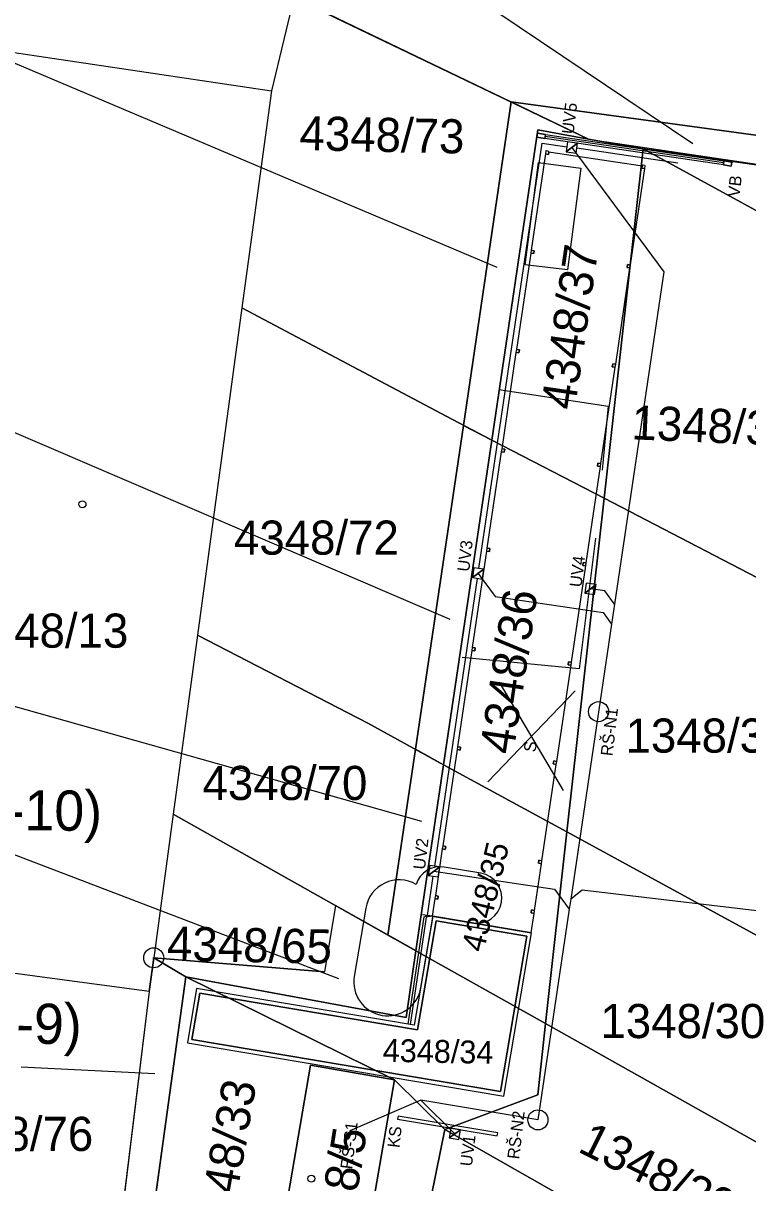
# Model space of a CAD drawing. Extents: x -735036 to -734743, y -1144813 to -1144181.
# Drawn here: x -734893.7 to -734857.6, y -1144559 to -1144501.3 of the extents above; entities that cross this region are included whole.
import ezdxf

# ---------------------------------------------------------------- set-up
doc = ezdxf.new("R2010")
doc.units = 0
for name, color, linetype in [('A3_BOURANÉ OBJEKTY', 7, 'Continuous'), ('A3_ODVODŇOVACÍ ŽLAB', 7, 'Continuous'), ('A3_SIT_OBJEKTY_N01', 7, 'Continuous'), ('A3_SIT_PNB', 7, 'Continuous'), ('CKKOTY', 7, 'Continuous'), ('CKSTENY_SRAF', 7, 'Continuous'), ('CKTEXTY_MALE', 7, 'Continuous'), ('Katastr_HRANICE DRÁHY', 7, 'Continuous'), ('Katastr_Hranice parcel', 7, 'Continuous'), ('Katastr_Parcelní čísla', 7, 'Continuous'), ('Katastr_pozemek SŽDC_šrafy', 7, 'Continuous'), ('Katastr_pozemek_ČD_šrafy', 7, 'Continuous'), ('Katastr_Značky kultur', 7, 'Continuous'), ('SO01_CKKANALIZACE_JEDNOTNA_PODZ_N', 7, 'Continuous'), ('SO05_CKKANALIZACE_JEDNOTNA_PODZ_N', 7, 'Continuous'), ('ZÁBORY_dočasné', 7, 'Continuous'), ('ZÁBORY_dočasné_šrafy', 7, 'Continuous')]:
    doc.layers.add(name, color=color, linetype=linetype)

msp = doc.modelspace()

# ---------------------------------------------------------------- linework, layer by layer
for p, q in [((-734866.625, -1144507.658), (-734866.057, -1144507.237)), ((-734871.293, -1144528.872), (-734870.725, -1144528.45)), ((-734865.695, -1144529.643), (-734865.127, -1144529.221)), ((-734873.494, -1144543.707), (-734872.926, -1144543.285)), ((-734872.456, -1144556.781), (-734871.88, -1144556.371))]:
    msp.add_line(p, q)
for points in [[(-734866.625, -1144507.658), (-734866.13, -1144507.731), (-734866.057, -1144507.237), (-734866.551, -1144507.163)], [(-734866.625, -1144507.658), (-734866.13, -1144507.731), (-734866.057, -1144507.237)], [(-734871.293, -1144528.872), (-734870.798, -1144528.945), (-734870.725, -1144528.45), (-734871.219, -1144528.377)], [(-734871.293, -1144528.872), (-734870.798, -1144528.945), (-734870.725, -1144528.45)], [(-734865.695, -1144529.643), (-734865.201, -1144529.716), (-734865.127, -1144529.221), (-734865.622, -1144529.148)], [(-734865.695, -1144529.643), (-734865.201, -1144529.716), (-734865.127, -1144529.221)], [(-734873.494, -1144543.707), (-734873, -1144543.78), (-734872.926, -1144543.285), (-734873.421, -1144543.212)], [(-734873.494, -1144543.707), (-734873, -1144543.78), (-734872.926, -1144543.285)], [(-734872.456, -1144556.781), (-734871.963, -1144556.864), (-734871.88, -1144556.371), (-734872.373, -1144556.288)], [(-734872.456, -1144556.781), (-734871.963, -1144556.864), (-734871.88, -1144556.371)]]:
    msp.add_lwpolyline(points, close=True)
at = {"layer": 'A3_BOURANÉ OBJEKTY'}
for p, q in [((-734866.751, -1144539.477), (-734869.95, -1144534.072)), ((-734866.175, -1144534.51), (-734870.526, -1144539.039))]:
    msp.add_line(p, q, dxfattribs=at)
msp.add_lwpolyline([(-734866.552, -1144513.548), (-734868.669, -1144513.299), (-734867.996, -1144508.198), (-734865.894, -1144508.483)], close=True, dxfattribs=at)
for points in [[(-734869.977, -1144519.507), (-734864.523, -1144520.336), (-734864.819, -1144523.525)], [(-734865.166, -1144526.906), (-734865.978, -1144533.409), (-734871.807, -1144532.846)]]:
    msp.add_lwpolyline(points, dxfattribs=at)
at = {"layer": 'A3_ODVODŇOVACÍ ŽLAB'}
for points in [[(-734870.972, -1144528.414), (-734867.824, -1144507.227), (-734866.588, -1144507.411)], [(-734861.049, -1144508.234), (-734866.093, -1144507.484)], [(-734873.174, -1144543.249), (-734871.046, -1144528.908)], [(-734874.496, -1144551.113), (-734873.702, -1144545.773), (-734873.54, -1144545.701), (-734873.249, -1144543.743)]]:
    msp.add_lwpolyline(points, dxfattribs=at)
at = {"layer": 'A3_SIT_OBJEKTY_N01'}
for p, q in [((-734867.491, -1144507.64), (-734867.62, -1144507.621)), ((-734867.487, -1144507.681), (-734867.483, -1144507.651)), ((-734862.694, -1144508.352), (-734862.823, -1144508.333)), ((-734873.262, -1144545.743), (-734874.2, -1144551.163)), ((-734874.036, -1144551.393), (-734873.099, -1144545.974)), ((-734868.356, -1144546.569), (-734873.262, -1144545.743)), ((-734873.099, -1144545.974), (-734868.587, -1144546.733)), ((-734869.725, -1144554.704), (-734868.356, -1144546.569)), ((-734868.587, -1144546.733), (-734869.889, -1144554.474)), ((-734885.047, -1144549.338), (-734885.503, -1144552.05)), ((-734874.2, -1144551.163), (-734885.047, -1144549.338)), ((-734885.273, -1144551.886), (-734884.883, -1144549.568)), ((-734884.883, -1144549.568), (-734874.036, -1144551.393)), ((-734885.503, -1144552.05), (-734869.725, -1144554.704)), ((-734869.889, -1144554.474), (-734885.273, -1144551.886)), ((-734875, -1144555.695), (-734875.026, -1144555.843)), ((-734875.026, -1144555.843), (-734870.057, -1144556.677)), ((-734870.032, -1144556.529), (-734875, -1144555.695)), ((-734870.057, -1144556.677), (-734870.032, -1144556.529))]:
    msp.add_line(p, q, dxfattribs=at)
for points in [[(-734867.659, -1144506.797), (-734867.689, -1144506.994), (-734868.084, -1144506.936), (-734868.055, -1144506.738), (-734867.659, -1144506.797)], [(-734888.44, -1144569.554), (-734887.65, -1144563.8), (-734885.58, -1144548.75), (-734874.6, -1144550.79), (-734868.084, -1144506.936)], [(-734858.772, -1144508.218), (-734867.674, -1144506.895)], [(-734867.631, -1144507.629), (-734867.652, -1144507.767), (-734867.504, -1144507.79), (-734867.487, -1144507.681)], [(-734862.834, -1144508.342), (-734862.838, -1144508.372), (-734862.855, -1144508.48), (-734862.706, -1144508.502), (-734862.686, -1144508.364)], [(-734858.391, -1144508.376), (-734858.786, -1144508.317), (-734858.757, -1144508.119), (-734858.361, -1144508.178), (-734858.391, -1144508.376)], [(-734868.216, -1144512.587), (-734868.365, -1144512.565), (-734868.387, -1144512.713), (-734868.238, -1144512.735), (-734868.216, -1144512.587)], [(-734863.419, -1144513.3), (-734863.567, -1144513.278), (-734863.589, -1144513.426), (-734863.441, -1144513.448), (-734863.419, -1144513.3)], [(-734868.951, -1144517.533), (-734869.099, -1144517.511), (-734869.122, -1144517.659), (-734868.973, -1144517.681), (-734868.951, -1144517.533)], [(-734864.154, -1144518.245), (-734864.302, -1144518.223), (-734864.324, -1144518.372), (-734864.176, -1144518.394), (-734864.154, -1144518.245)], [(-734869.686, -1144522.478), (-734869.834, -1144522.456), (-734869.856, -1144522.605), (-734869.708, -1144522.627), (-734869.686, -1144522.478)], [(-734864.889, -1144523.191), (-734865.037, -1144523.169), (-734865.059, -1144523.317), (-734864.911, -1144523.339), (-734864.889, -1144523.191)], [(-734870.421, -1144527.424), (-734870.569, -1144527.402), (-734870.591, -1144527.55), (-734870.443, -1144527.572), (-734870.421, -1144527.424)], [(-734865.623, -1144528.137), (-734865.772, -1144528.115), (-734865.794, -1144528.263), (-734865.645, -1144528.285), (-734865.623, -1144528.137)], [(-734871.156, -1144532.37), (-734871.304, -1144532.348), (-734871.326, -1144532.496), (-734871.178, -1144532.518), (-734871.156, -1144532.37)], [(-734866.358, -1144533.082), (-734866.507, -1144533.06), (-734866.529, -1144533.209), (-734866.38, -1144533.231), (-734866.358, -1144533.082)], [(-734871.89, -1144537.315), (-734872.039, -1144537.293), (-734872.061, -1144537.442), (-734871.912, -1144537.464), (-734871.89, -1144537.315)], [(-734867.093, -1144538.028), (-734867.241, -1144538.006), (-734867.263, -1144538.155), (-734867.115, -1144538.177), (-734867.093, -1144538.028)], [(-734872.625, -1144542.261), (-734872.774, -1144542.239), (-734872.796, -1144542.387), (-734872.647, -1144542.41), (-734872.625, -1144542.261)], [(-734867.828, -1144542.974), (-734867.976, -1144542.952), (-734867.998, -1144543.1), (-734867.85, -1144543.122), (-734867.828, -1144542.974)], [(-734873.163, -1144544.86), (-734873.015, -1144544.882), (-734872.993, -1144544.734), (-734873.141, -1144544.712), (-734873.163, -1144544.86)], [(-734868.195, -1144545.447), (-734868.344, -1144545.425), (-734868.366, -1144545.573), (-734868.217, -1144545.595), (-734868.195, -1144545.447)], [(-734873.262, -1144545.743), (-734873.293, -1144545.738), (-734873.603, -1144545.787), (-734874.397, -1144551.13)]]:
    msp.add_lwpolyline(points, dxfattribs=at)
for points in [[(-734868.055, -1144506.738), (-734868.084, -1144506.936), (-734867.689, -1144506.994), (-734867.659, -1144506.797)], [(-734867.659, -1144506.797), (-734858.757, -1144508.119), (-734858.786, -1144508.317), (-734867.689, -1144506.994)], [(-734869.708, -1144522.627), (-734869.856, -1144522.605), (-734870.569, -1144527.402), (-734870.421, -1144527.424), (-734870.443, -1144527.572), (-734870.591, -1144527.55), (-734871.304, -1144532.348), (-734871.156, -1144532.37), (-734871.178, -1144532.518), (-734871.326, -1144532.496), (-734872.039, -1144537.293), (-734871.89, -1144537.315), (-734871.912, -1144537.464), (-734872.061, -1144537.442), (-734872.774, -1144542.239), (-734872.625, -1144542.261), (-734872.647, -1144542.41), (-734872.796, -1144542.387), (-734873.141, -1144544.712), (-734872.993, -1144544.734), (-734873.015, -1144544.882), (-734873.163, -1144544.86), (-734873.293, -1144545.738), (-734868.362, -1144546.568), (-734868.217, -1144545.595), (-734868.366, -1144545.573), (-734868.344, -1144545.425), (-734868.195, -1144545.447), (-734867.85, -1144543.122), (-734867.998, -1144543.1), (-734867.976, -1144542.952), (-734867.828, -1144542.974), (-734867.115, -1144538.177), (-734867.263, -1144538.155), (-734867.241, -1144538.006), (-734867.093, -1144538.028), (-734866.38, -1144533.231), (-734866.529, -1144533.209), (-734866.507, -1144533.06), (-734866.358, -1144533.082), (-734865.645, -1144528.285), (-734865.794, -1144528.263), (-734865.772, -1144528.115), (-734865.623, -1144528.137), (-734864.911, -1144523.339), (-734865.059, -1144523.317), (-734865.037, -1144523.169), (-734864.889, -1144523.191), (-734864.176, -1144518.394), (-734864.324, -1144518.372), (-734864.302, -1144518.223), (-734864.154, -1144518.245), (-734863.441, -1144513.448), (-734863.589, -1144513.426), (-734863.567, -1144513.278), (-734863.419, -1144513.3), (-734862.706, -1144508.502), (-734862.855, -1144508.48), (-734862.838, -1144508.372), (-734862.937, -1144508.357), (-734867.389, -1144507.696), (-734867.487, -1144507.681), (-734867.504, -1144507.79), (-734867.652, -1144507.767), (-734868.365, -1144512.565), (-734868.216, -1144512.587), (-734868.238, -1144512.735), (-734868.387, -1144512.713), (-734869.099, -1144517.511), (-734868.951, -1144517.533), (-734868.973, -1144517.681), (-734869.122, -1144517.659), (-734869.834, -1144522.456), (-734869.686, -1144522.478)], [(-734858.786, -1144508.317), (-734858.391, -1144508.376), (-734858.361, -1144508.178), (-734858.757, -1144508.119)], [(-734869.725, -1144554.704), (-734868.356, -1144546.569), (-734873.262, -1144545.743), (-734874.2, -1144551.163), (-734885.047, -1144549.338), (-734885.503, -1144552.05)], [(-734869.889, -1144554.474), (-734868.587, -1144546.733), (-734873.099, -1144545.974), (-734874.036, -1144551.393), (-734884.883, -1144549.568), (-734885.273, -1144551.886)], [(-734875.026, -1144555.843), (-734870.057, -1144556.677), (-734870.032, -1144556.529), (-734875, -1144555.695)]]:
    msp.add_lwpolyline(points, close=True, dxfattribs=at)
for centre, start, end in [((-734867.621, -1144507.63), 81.54908, 171.54908), ((-734867.493, -1144507.65), 351.54908, 81.54908), ((-734862.824, -1144508.343), 81.54908, 171.54908), ((-734862.695, -1144508.362), 351.54908, 81.54908)]:
    msp.add_arc(centre, 0.01, start, end, dxfattribs=at)
at = {"layer": 'A3_SIT_PNB'}
for points in [[(-734870.874, -1144543.6), (-734872.698, -1144543.293)], [(-734876.611, -1144545.332), (-734877.183, -1144548.734)], [(-734873.86, -1144549.293), (-734873.287, -1144545.891), (-734873.262, -1144545.743), (-734873.114, -1144545.768), (-734871.29, -1144546.075)]]:
    msp.add_lwpolyline(points, dxfattribs=at)
for centre, radius, start, end in [((-734872.906, -1144544.531), 1.255, 80.4474, 162.539), ((-734871.082, -1144544.838), 1.255, 260.44926, 80.44926), ((-734874.949, -1144545.612), 1.685, 59.88428, 170.44851), ((-734875.521, -1144549.014), 1.685, 170.44926, 350.44926)]:
    msp.add_arc(centre, radius, start, end, dxfattribs=at)
at = {"layer": 'CKKOTY'}
msp.add_line((-734873.293, -1144545.738), (-734873.787, -1144545.665), dxfattribs=at)
at = {"layer": 'CKSTENY_SRAF'}
msp.add_line((-734885.58, -1144548.75), (-734886.194, -1144553.213), dxfattribs=at)
at = {"layer": 'CKTEXTY_MALE'}
for points in [[(-734873.87, -1144554.906), (-734877.406, -1144556.428)], [(-734877.406, -1144556.428), (-734877.429, -1144556.626)]]:
    msp.add_lwpolyline(points, dxfattribs=at)
at = {"layer": 'Katastr_HRANICE DRÁHY'}
for points in [[(-734894.14, -1144502.71), (-734881.31, -1144504.63)], [(-734881.31, -1144504.63), (-734882.78, -1144515.44)], [(-734882.78, -1144515.44), (-734885, -1144531.74)], [(-734885, -1144531.74), (-734886.21, -1144540.66)], [(-734886.21, -1144540.66), (-734887.18, -1144547.81)], [(-734887.18, -1144547.81), (-734885.58, -1144548.75)], [(-734885.58, -1144548.75), (-734887.65, -1144563.8)]]:
    msp.add_lwpolyline(points, dxfattribs=at)
at = {"layer": 'Katastr_Hranice parcel'}
for points in [[(-734865.5, -1144507.03), (-734912.56, -1144484.42)], [(-734868.03, -1144506.57), (-734870.33, -1144522.02)], [(-734868.03, -1144506.57), (-734865.5, -1144507.03)], [(-734865.5, -1144507.03), (-734862.79, -1144507.52)], [(-734862.79, -1144507.52), (-734864.73, -1144524.92)], [(-734852.42, -1144508.98), (-734862.79, -1144507.52)], [(-734852.87, -1144512.92), (-734862.79, -1144507.52)], [(-734882.78, -1144515.44), (-734872.29, -1144521)], [(-734872.29, -1144521), (-734870.33, -1144522.02)], [(-734870.33, -1144522.02), (-734872.73, -1144538.19)], [(-734870.33, -1144522.02), (-734864.73, -1144524.92)], [(-734866.58, -1144541.54), (-734864.73, -1144524.92)], [(-734864.73, -1144524.92), (-734851.62, -1144531.72)], [(-734876.5, -1144536.13), (-734885, -1144531.74)], [(-734872.73, -1144538.19), (-734876.5, -1144536.13)], [(-734872.73, -1144538.19), (-734874.11, -1144547.46)], [(-734866.58, -1144541.54), (-734872.73, -1144538.19)], [(-734874.11, -1144547.46), (-734886.21, -1144540.66)], [(-734867.65, -1144551.09), (-734866.58, -1144541.54)], [(-734852.48, -1144549.23), (-734866.58, -1144541.54)], [(-734887.41, -1144549.49), (-734900.43, -1144547.74)], [(-734874.11, -1144547.46), (-734874.6, -1144550.79)], [(-734867.65, -1144551.09), (-734874.11, -1144547.46)], [(-734887.18, -1144547.81), (-734887.41, -1144549.49)], [(-734874.6, -1144550.79), (-734885.58, -1144548.75)], [(-734885.58, -1144548.75), (-734875.18, -1144553.88)], [(-734868.04, -1144554.63), (-734867.65, -1144551.09)], [(-734853.62, -1144558.97), (-734867.65, -1144551.09)], [(-734881.1, -1144563.24), (-734879.37, -1144553.15)], [(-734879.37, -1144553.15), (-734875.18, -1144553.88)], [(-734875.18, -1144553.88), (-734876.93, -1144563.95)], [(-734875.18, -1144553.88), (-734872.67, -1144556.37)], [(-734872.67, -1144556.37), (-734868.04, -1144554.63)], [(-734875.6, -1144570.76), (-734872.67, -1144556.37)], [(-734854.52, -1144566.67), (-734872.67, -1144556.37)]]:
    msp.add_lwpolyline(points, dxfattribs=at)
at = {"layer": 'Katastr_pozemek SŽDC_šrafy'}
for points in [[(-734862.79, -1144507.52), (-734865.5, -1144507.03), (-734868.03, -1144506.57), (-734870.33, -1144522.02), (-734864.73, -1144524.92), (-734862.79, -1144507.52)], [(-734850.35, -1144520.8), (-734853.72, -1144520.41), (-734852.87, -1144512.92), (-734862.79, -1144507.52), (-734864.73, -1144524.92), (-734851.62, -1144531.72), (-734850.35, -1144520.8)], [(-734852.42, -1144508.98), (-734862.79, -1144507.52), (-734852.87, -1144512.92), (-734852.42, -1144508.98)], [(-734864.73, -1144524.92), (-734870.33, -1144522.02), (-734872.73, -1144538.19), (-734866.58, -1144541.54), (-734864.73, -1144524.92)], [(-734851.62, -1144531.72), (-734864.73, -1144524.92), (-734866.58, -1144541.54), (-734852.48, -1144549.23), (-734851.65, -1144542.13), (-734852.82, -1144541.99), (-734851.62, -1144531.72)], [(-734866.58, -1144541.54), (-734872.73, -1144538.19), (-734874.11, -1144547.46), (-734867.65, -1144551.09), (-734866.58, -1144541.54)], [(-734852.48, -1144549.23), (-734866.58, -1144541.54), (-734867.65, -1144551.09), (-734853.62, -1144558.97), (-734852.48, -1144549.23)], [(-734867.65, -1144551.09), (-734874.11, -1144547.46), (-734874.6, -1144550.79), (-734885.58, -1144548.75), (-734875.18, -1144553.88), (-734872.67, -1144556.37), (-734868.04, -1144554.63), (-734867.65, -1144551.09)], [(-734879.37, -1144553.15), (-734875.18, -1144553.88), (-734885.58, -1144548.75), (-734887.65, -1144563.8), (-734875.6, -1144570.76), (-734872.67, -1144556.37), (-734875.18, -1144553.88), (-734876.93, -1144563.95), (-734881.1, -1144563.24), (-734879.37, -1144553.15)], [(-734867.65, -1144551.09), (-734868.04, -1144554.63), (-734872.67, -1144556.37), (-734854.52, -1144566.67), (-734853.62, -1144558.97), (-734867.65, -1144551.09)], [(-734879.37, -1144553.15), (-734881.1, -1144563.24), (-734876.93, -1144563.95), (-734875.18, -1144553.88), (-734879.37, -1144553.15)], [(-734872.67, -1144556.37), (-734875.6, -1144570.76), (-734874.46, -1144571.42), (-734858.99, -1144579.44), (-734858.08, -1144572.26), (-734855.22, -1144572.62), (-734854.52, -1144566.67), (-734872.67, -1144556.37)]]:
    msp.add_lwpolyline(points, dxfattribs=at)
at = {"layer": 'Katastr_pozemek_ČD_šrafy'}
for points in [[(-734850.16, -1144494.56), (-734850.37, -1144495.22), (-734851.22, -1144494.96), (-734851.02, -1144494.29), (-734876.91, -1144486.38), (-734880.187, -1144499.973), (-734865.5, -1144507.03), (-734862.79, -1144507.52), (-734852.42, -1144508.98), (-734833.68, -1144511.64), (-734832.99, -1144511.73), (-734832.95, -1144511.4), (-734831.84, -1144499.97), (-734850.16, -1144494.56)], [(-734868.03, -1144506.57), (-734865.5, -1144507.03), (-734880.187, -1144499.973), (-734881.31, -1144504.63), (-734882.78, -1144515.44), (-734872.29, -1144521), (-734870.33, -1144522.02), (-734868.03, -1144506.57)], [(-734870.33, -1144522.02), (-734872.29, -1144521), (-734882.78, -1144515.44), (-734885, -1144531.74), (-734876.5, -1144536.13), (-734872.73, -1144538.19), (-734870.33, -1144522.02)], [(-734872.73, -1144538.19), (-734876.5, -1144536.13), (-734885, -1144531.74), (-734886.21, -1144540.66), (-734874.11, -1144547.46), (-734872.73, -1144538.19)], [(-734886.21, -1144540.66), (-734887.18, -1144547.81), (-734885.58, -1144548.75), (-734874.6, -1144550.79), (-734874.11, -1144547.46), (-734886.21, -1144540.66)]]:
    msp.add_lwpolyline(points, dxfattribs=at)
at = {"layer": 'Katastr_Značky kultur'}
msp.add_line((-734887.23, -1144547.81), (-734887.13, -1144547.81), dxfattribs=at)
for centre, radius in [((-734890.73, -1144525.22), 0.175), ((-734887.18, -1144547.81), 0.499), ((-734879.32, -1144558.81), 0.175)]:
    msp.add_circle(centre, radius, dxfattribs=at)
at = {"layer": 'SO01_CKKANALIZACE_JEDNOTNA_PODZ_N'}
msp.add_lwpolyline([(-734852.237, -1144546.036), (-734854.223, -1144545.804), (-734854.72, -1144545.746), (-734865.823, -1144544.448), (-734866.393, -1144544.885)], dxfattribs=at)
at = {"layer": 'SO05_CKKANALIZACE_JEDNOTNA_PODZ_N'}
msp.add_line((-734872.168, -1144556.576), (-734873.869, -1144554.902), dxfattribs=at)
for points in [[(-734866.341, -1144507.447), (-734861.751, -1144513.639), (-734864.21, -1144530.193), (-734864.357, -1144531.183), (-734866.393, -1144544.885), (-734866.467, -1144545.379), (-734868.027, -1144555.885), (-734873.869, -1144554.902)], [(-734871.009, -1144528.661), (-734870.152, -1144529.816), (-734864.775, -1144530.615), (-734864.357, -1144531.183)], [(-734864.21, -1144530.193), (-734864.695, -1144529.538), (-734865.411, -1144529.432)], [(-734873.21, -1144543.496), (-734867.201, -1144544.389), (-734866.467, -1144545.379)]]:
    msp.add_lwpolyline(points, dxfattribs=at)
for centre in [(-734865.006, -1144535.549), (-734868.027, -1144555.884)]:
    msp.add_circle(centre, 0.5, dxfattribs=at)
at = {"layer": 'ZÁBORY_dočasné'}
for p, q in [((-734884.98, -1144490.683), (-734860.304, -1144507.242)), ((-734898.69, -1144501.308), (-734870.076, -1144513.411)), ((-734871.733, -1144521.29), (-734869.357, -1144505.177)), ((-734869.357, -1144505.177), (-734865.5, -1144507.03)), ((-734869.357, -1144505.177), (-734857.053, -1144506.856)), ((-734868.03, -1144506.57), (-734870.33, -1144522.02)), ((-734865.5, -1144507.03), (-734868.03, -1144506.57)), ((-734865.5, -1144507.03), (-734852.42, -1144508.98)), ((-734901.785, -1144518.351), (-734872.426, -1144530.945)), ((-734874.131, -1144537.425), (-734871.733, -1144521.29)), ((-734870.33, -1144522.02), (-734871.733, -1144521.29)), ((-734870.326, -1144522.022), (-734872.73, -1144538.19)), ((-734903.829, -1144532.552), (-734873.838, -1144540.999)), ((-734875.505, -1144546.676), (-734874.131, -1144537.425)), ((-734872.73, -1144538.19), (-734874.131, -1144537.425)), ((-734874.106, -1144547.462), (-734872.73, -1144538.19)), ((-734894.266, -1144542.611), (-734877.968, -1144548.842)), ((-734878.111, -1144545.211), (-734878.665, -1144548.509)), ((-734874.106, -1144547.462), (-734878.111, -1144545.211)), ((-734874.6, -1144550.79), (-734874.106, -1144547.462)), ((-734887.41, -1144549.49), (-734887.18, -1144547.81)), ((-734887.18, -1144547.81), (-734885.58, -1144548.75)), ((-734887.18, -1144547.81), (-734878.665, -1144548.509)), ((-734885.58, -1144548.75), (-734887.65, -1144563.8)), ((-734885.58, -1144548.75), (-734874.6, -1144550.79)), ((-734887.41, -1144549.49), (-734889.125, -1144563.502)), ((-734893.792, -1144553.248), (-734887.128, -1144553.577))]:
    msp.add_line(p, q, dxfattribs=at)
at = {"layer": 'ZÁBORY_dočasné_šrafy'}
for points in [[(-734857.053, -1144506.856), (-734869.357, -1144505.177), (-734865.5, -1144507.03), (-734852.42, -1144508.98), (-734832.99, -1144511.73), (-734831.84, -1144499.97), (-734857.053, -1144506.856)], [(-734871.733, -1144521.29), (-734870.33, -1144522.02), (-734868.03, -1144506.57), (-734865.5, -1144507.03), (-734869.357, -1144505.177), (-734871.733, -1144521.29)], [(-734874.131, -1144537.425), (-734872.73, -1144538.19), (-734870.326, -1144522.022), (-734871.733, -1144521.29), (-734871.733, -1144521.29), (-734874.131, -1144537.425)], [(-734875.505, -1144546.676), (-734874.106, -1144547.462), (-734872.73, -1144538.19), (-734874.131, -1144537.425), (-734875.505, -1144546.676)], [(-734878.111, -1144545.211), (-734878.665, -1144548.509), (-734887.18, -1144547.81), (-734885.58, -1144548.75), (-734874.6, -1144550.79), (-734874.106, -1144547.462), (-734878.111, -1144545.211)], [(-734885.58, -1144548.75), (-734887.18, -1144547.81), (-734887.41, -1144549.49), (-734889.125, -1144563.502), (-734887.65, -1144563.8), (-734885.58, -1144548.75)]]:
    msp.add_lwpolyline(points, dxfattribs=at)

# ---------------------------------------------------------------- texts
at = {"layer": 'CKTEXTY_MALE'}
for s, rotation, p in [('UV5', 83.326, (-734866.251, -1144506.804)), ('VB', 83.326, (-734857.985, -1144509.937)), ('UV3', 83.326, (-734871.455, -1144528.601)), ('UV4', 83.326, (-734865.857, -1144529.372)), ('RŠ-N1', 83.326, (-734864.312, -1144537.784)), ('S', 83.326, (-734868.143, -1144537.587)), ('UV2', 83.326, (-734873.659, -1144543.438)), ('RŠ-N2', 83.326, (-734868.964, -1144557.864)), ('RŠ-S1', 83.32599, (-734877.284, -1144558.362)), ('KS', 83.326, (-734874.936, -1144557.297)), ('UV1', 83.326, (-734871.316, -1144558.219))]:
    msp.add_text(s, height=0.6, rotation=rotation, dxfattribs=at).set_placement(p)
at = {"layer": 'Katastr_Parcelní čísla'}
for s, height, rotation, p in [('4348/73', 1.7, 358.76214, (-734879.926, -1144507.576)), ('4348/37', 1.7, 81.65502, (-734866.195, -1144520.566)), ('1348/32', 1.7, 357.57765, (-734863.39, -1144521.981)), ('4348/36', 1.7, 81.4482, (-734869.257, -1144537.728)), ('4348/35', 1.14, 76.51791, (-734870.739, -1144547.577)), ('4348/65', 1.7, 358.90416, (-734886.526, -1144547.947)), ('4348/34', 1.14, 358.85997, (-734875.77, -1144552.985)), ('4348/33', 1.7, 80.02647, (-734883.471, -1144562.144)), ('4348/5', 1.7, 80.96139, (-734877.631, -1144563.281)), ('1348/29', 1.7, 333.39276, (-734866.103, -1144557.435))]:
    msp.add_text(s, height=height, rotation=rotation, dxfattribs=at).set_placement(p)
for s, p in [('4348/72', (-734883.177, -1144527.73)), ('4348/13', (-734896.662, -1144532.363)), ('1348/31', (-734863.663, -1144537.59)), ('4348/70', (-734884.747, -1144539.95)), ('1348/30', (-734864.914, -1144551.81)), ('4348/76', (-734898.411, -1144557.43))]:
    msp.add_text(s, height=1.7, dxfattribs=at).set_placement(p)
at = {"layer": 'ZÁBORY_dočasné'}
for s, p in [('DOČASNÝ ZÁBOR POZEMKU (DZ-10)', (-734936.865, -1144540.985)), ('DOČASNÝ ZÁBOR POZEMKU (DZ-9)', (-734936.391, -1144551.621))]:
    msp.add_text(s, height=2, rotation=359.37885, dxfattribs=at).set_placement(p)

doc.saveas('drawing.dxf')
